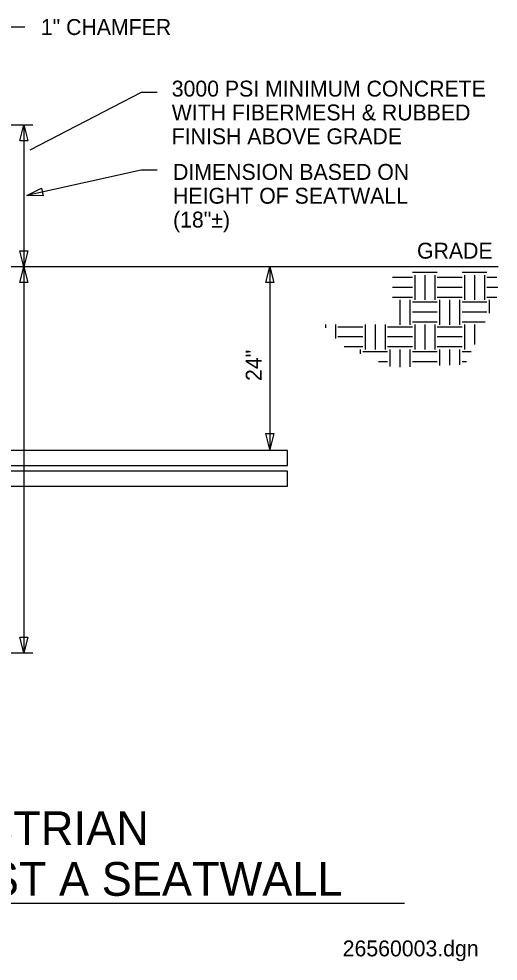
# Model space of a CAD drawing. Extents: x 10109.1 to 10158.1, y 10066 to 10132.7.
# Drawn here: x 10138.01 to 10158.12, y 10066.02 to 10105.53 of the extents above; entities that cross this region are included whole.
import ezdxf

# ---------------------------------------------------------------- set-up
doc = ezdxf.new("R2010")
doc.units = 0
for name, color, linetype in [('G-ANNO-TEXT', 7, 'Continuous'), ('G-DETL-LINE', 7, 'Continuous'), ('G-DETL-OTLN', 7, 'Continuous'), ('G-DETL-PATT', 7, 'Continuous')]:
    doc.layers.add(name, color=color, linetype=linetype)

msp = doc.modelspace()

# ---------------------------------------------------------------- linework, layer by layer
at = {"layer": 'G-ANNO-TEXT'}
for p, q in [((10138.27, 10105.191), (10137.604, 10105.191)), ((10143.149, 10102.448), (10138.472, 10100.032)), ((10143.816, 10102.448), (10143.149, 10102.448)), ((10135.84, 10101.09), (10138.597, 10101.09)), ((10138.222, 10101.09), (10138.222, 10095.139)), ((10143.149, 10099.186), (10138.343, 10098.128)), ((10143.816, 10099.186), (10143.149, 10099.186)), ((10138.222, 10095.139), (10138.222, 10078.945)), ((10148.547, 10095.139), (10148.547, 10087.472)), ((10136.402, 10078.945), (10138.597, 10078.945)), ((10113.422, 10068.447), (10154.193, 10068.447))]:
    msp.add_line(p, q, dxfattribs=at)
for points in [[(10138.055, 10100.423), (10138.222, 10101.09), (10138.389, 10100.423)], [(10139.03, 10098.108), (10138.343, 10098.128), (10138.958, 10098.434)], [(10138.389, 10095.805), (10138.222, 10095.139), (10138.055, 10095.805)], [(10138.056, 10094.472), (10138.222, 10095.139), (10138.389, 10094.472)], [(10148.38, 10094.472), (10148.547, 10095.139), (10148.714, 10094.472)], [(10148.714, 10088.139), (10148.547, 10087.472), (10148.38, 10088.139)], [(10138.389, 10079.611), (10138.222, 10078.945), (10138.056, 10079.611)]]:
    msp.add_lwpolyline(points, close=True, dxfattribs=at)
at = {"layer": 'G-DETL-LINE'}
msp.add_line((10158.123, 10095.139), (10136.027, 10095.139), dxfattribs=at)
at = {"layer": 'G-DETL-OTLN'}
for p, q in [((10149.282, 10087.435), (10134.724, 10087.435)), ((10149.282, 10086.81), (10149.282, 10087.435)), ((10134.729, 10086.81), (10149.282, 10086.81)), ((10149.282, 10086.565), (10134.543, 10086.565)), ((10149.282, 10085.94), (10149.282, 10086.565)), ((10134.541, 10085.94), (10149.282, 10085.94))]:
    msp.add_line(p, q, dxfattribs=at)
at = {"layer": 'G-DETL-PATT'}
for p, q in [((10154.528, 10094.685), (10153.686, 10094.685)), ((10155.569, 10094.894), (10154.528, 10094.894)), ((10154.632, 10094.79), (10154.632, 10093.748)), ((10155.048, 10094.79), (10155.048, 10093.748)), ((10155.465, 10094.79), (10155.465, 10093.748)), ((10156.611, 10094.685), (10155.569, 10094.685)), ((10157.653, 10094.894), (10156.611, 10094.894)), ((10156.715, 10094.79), (10156.715, 10093.748)), ((10157.132, 10094.79), (10157.132, 10093.748)), ((10157.548, 10094.79), (10157.548, 10093.748)), ((10158.07, 10094.685), (10157.653, 10094.685)), ((10154.528, 10094.269), (10153.686, 10094.269)), ((10156.611, 10094.269), (10155.569, 10094.269)), ((10158.107, 10094.269), (10157.653, 10094.269)), ((10154.528, 10093.852), (10153.686, 10093.852)), ((10156.611, 10093.852), (10155.569, 10093.852)), ((10158.061, 10093.852), (10157.653, 10093.852)), ((10153.999, 10093.748), (10153.999, 10092.706)), ((10154.416, 10093.748), (10154.416, 10092.706)), ((10155.569, 10093.651), (10154.528, 10093.651)), ((10155.666, 10093.748), (10155.666, 10092.706)), ((10156.082, 10093.748), (10156.082, 10092.706)), ((10156.499, 10093.748), (10156.499, 10092.706)), ((10157.653, 10093.651), (10156.611, 10093.651)), ((10157.749, 10093.748), (10157.749, 10093.19)), ((10155.569, 10093.234), (10154.528, 10093.234)), ((10157.653, 10093.234), (10156.611, 10093.234)), ((10150.882, 10092.714), (10150.882, 10092.571)), ((10151.298, 10092.714), (10151.298, 10092.13)), ((10152.444, 10092.609), (10151.403, 10092.609)), ((10152.548, 10092.714), (10152.548, 10091.672)), ((10152.965, 10092.714), (10152.965, 10091.672)), ((10153.382, 10092.714), (10153.382, 10091.672)), ((10154.528, 10092.609), (10153.486, 10092.609)), ((10155.569, 10092.818), (10154.528, 10092.818)), ((10154.632, 10092.714), (10154.632, 10091.672)), ((10155.048, 10092.714), (10155.048, 10091.672)), ((10155.465, 10092.714), (10155.465, 10091.672)), ((10156.611, 10092.609), (10155.569, 10092.609)), ((10157.573, 10092.818), (10156.611, 10092.818)), ((10156.715, 10092.714), (10156.715, 10091.672)), ((10157.132, 10092.714), (10157.132, 10091.88)), ((10152.444, 10092.193), (10151.403, 10092.193)), ((10154.528, 10092.193), (10153.486, 10092.193)), ((10156.611, 10092.193), (10155.569, 10092.193)), ((10151.582, 10091.672), (10151.582, 10091.668)), ((10152.444, 10091.776), (10151.663, 10091.776)), ((10152.332, 10091.672), (10152.332, 10091.489)), ((10153.486, 10091.575), (10152.444, 10091.575)), ((10154.528, 10091.776), (10153.486, 10091.776)), ((10153.582, 10091.672), (10153.582, 10090.953)), ((10153.999, 10091.672), (10153.999, 10090.922)), ((10154.416, 10091.672), (10154.416, 10090.939)), ((10155.569, 10091.575), (10154.528, 10091.575)), ((10156.611, 10091.776), (10155.569, 10091.776)), ((10155.666, 10091.672), (10155.666, 10090.991)), ((10156.082, 10091.672), (10156.082, 10091.009)), ((10156.499, 10091.672), (10156.499, 10091.026)), ((10156.988, 10091.575), (10156.611, 10091.575)), ((10153.486, 10091.158), (10153.104, 10091.158)), ((10155.569, 10091.158), (10154.528, 10091.158)), ((10156.792, 10091.158), (10156.611, 10091.158))]:
    msp.add_line(p, q, dxfattribs=at)

# ---------------------------------------------------------------- texts
at = {"layer": 'G-ANNO-TEXT'}
for s, height, p in [('1" CHAMFER', 0.6667, (10138.937, 10104.857)), ('3000 PSI MINIMUM CONCRETE', 0.66667, (10144.428, 10102.275)), ('WITH FIBERMESH & RUBBED', 0.66667, (10144.428, 10101.275)), ('FINISH ABOVE GRADE', 0.66667, (10144.428, 10100.275)), ('DIMENSION BASED ON', 0.66667, (10144.483, 10098.782)), ('HEIGHT OF SEATWALL', 0.66667, (10144.483, 10097.782)), ('(18"±)', 0.6667, (10144.483, 10096.782)), ('GRADE', 0.6667, (10154.719, 10095.479)), ('TYPICAL PEDESTRIAN', 1.41667, (10122.936, 10070.884)), ('LIGHT POLE BASE AGAINST A SEATWALL', 1.41667, (10113.59, 10068.759)), ('26560003.dgn', 0.66667, (10151.601, 10066.22))]:
    msp.add_text(s, height=height, dxfattribs=at).set_placement(p)
msp.add_text('24"', height=0.6667, rotation=90, dxfattribs=at).set_placement((10148.201, 10090.348))

doc.saveas('drawing.dxf')
